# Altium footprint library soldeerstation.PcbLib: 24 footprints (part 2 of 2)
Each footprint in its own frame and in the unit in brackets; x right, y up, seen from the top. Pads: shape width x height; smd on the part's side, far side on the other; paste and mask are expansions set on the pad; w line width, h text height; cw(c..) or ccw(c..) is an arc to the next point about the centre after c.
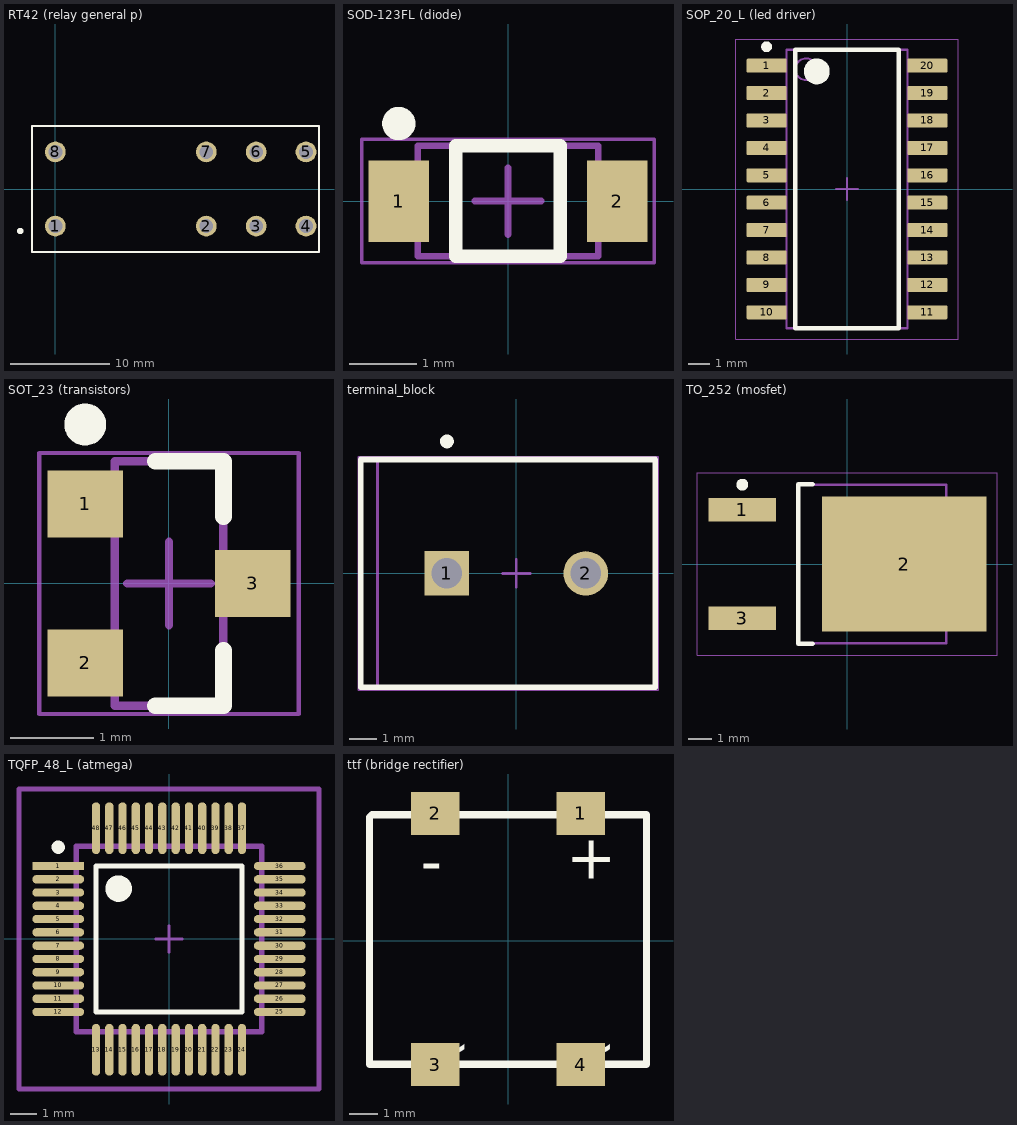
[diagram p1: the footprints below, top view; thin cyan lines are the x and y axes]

## RT42 (relay general p) [mm]
pads (8):
  round 2.1 hole 1.4: 1(0,-3.75) 2(15.26,-3.75) 3(20.3,-3.75) 4(25.34,-3.75) 5(25.34,3.75) 6(20.3,3.75) 7(15.26,3.75) 8(0,3.75)
Top Overlay:
  circle w0.4: c-3.547,-4.246 r0.126
  lines w0.2: -2.35,-6.35 -2.35,6.35 26.65,6.35 26.65,-6.35 -2.35,-6.35
Mechanical 13:
  lines w0.2: -2.35,-6.35 -2.35,6.35 26.65,6.35 26.65,-6.35 -2.35,-6.35
3D body "RT424005.stp": height 15.86, standoff -2.94, extent -2.21,-6.35 26.79,6.35

## SOD-123FL (diode) [mm] "SOD, 2-Leads, Body 2.7x1.65mm"
height 1
pads (2):
  rect 0.91x1.22 smd: 1(-1.635,0) 2(1.635,0)
Top Overlay:
  circle w0.25: c-1.635,1.16 r0.125
  lines w0.2: -0.78,-0.825 0.78,-0.825 0.78,0.825 -0.78,0.825 -0.78,-0.825
Mechanical 13:
  lines w0.1: -1.35,-0.825 1.35,-0.825 1.35,0.825 -1.35,0.825 -1.35,-0.825
Mechanical 15:
  lines w0.05: -2.19,-0.925 2.19,-0.925 2.19,0.925 -2.19,0.925 -2.19,-0.925
  lines w0.1: -0.5,0 0.5,0 ; 0,-0.5 0,0.5
3D body: height 1, standoff 0, extent -1.35,-0.825 1.35,0.825

## SOP_20_L (led driver) [mm] "SOIC,20-Leads,Body 12.9x5.6mm,Pitch 1.27mm,IPC Low Density"
height 2
pads (20):
  rrect15% 1.85x0.65 smd: 1(-3.725,5.715) 2(-3.725,4.445) 3(-3.725,3.175) 4(-3.725,1.905) 5(-3.725,0.635) 6(-3.725,-0.635) 7(-3.725,-1.905) 8(-3.725,-3.175) 9(-3.725,-4.445) 10(-3.725,-5.715) 11(3.725,-5.715) 12(3.725,-4.445) 13(3.725,-3.175) 14(3.725,-1.905) 15(3.725,-0.635) 16(3.725,0.635) 17(3.725,1.905) 18(3.725,3.175) 19(3.725,4.445) 20(3.725,5.715)
Top Overlay:
  circle w0.6: c-1.4,5.45 r0.3
  circle w0.25: c-3.725,6.59 r0.125
  lines w0.2: -2.4,-6.45 2.4,-6.45 2.4,6.45 -2.4,6.45 -2.4,-6.45
Mechanical 1:
  text ".Designator" at -1.524,-0.508 h1.02
Mechanical 13:
  circle w0.1: c-1.9,5.55 r0.5
  lines w0.1: -2.8,-6.45 2.8,-6.45 2.8,6.45 -2.8,6.45 -2.8,-6.45
Mechanical 15:
  lines w0.05: -5.15,-6.95 5.15,-6.95 5.15,6.95 -5.15,6.95 -5.15,-6.95
  lines w0.1: -0.5,0 0.5,0 ; 0,-0.5 0,0.5
3D body: height 2, standoff 0.05, extent -2.8,-6.45 2.8,6.45

## SOT_23 (transistors) [mm] "SOT23, 3-Leads, Body 2.92x1.3mm, Pitch 0.95mm"
height 1.11
pads (3):
  rect 0.9x0.8 smd: 1(-1,0.95) 2(-1,-0.95) 3(1,0)
Top Overlay:
  circle w0.25: c-1,1.9 r0.125
  lines w0.2: -0.165,-1.46 0.65,-1.46 0.65,-0.8 ; -0.165,1.46 0.65,1.46 0.65,0.8
Mechanical 13:
  lines w0.1: -0.65,-1.46 -0.65,1.46 0.65,1.46 0.65,-1.46 -0.65,-1.46
Mechanical 15:
  lines w0.05: -1.55,-1.56 -1.55,1.56 1.55,1.56 1.55,-1.56 -1.55,-1.56
  lines w0.1: -0.5,0 0.5,0 ; 0,-0.5 0,0.5
3D body: height 1.11, standoff 0.01, extent -0.65,-1.46 0.65,1.46

## terminal_block [mm] "Female Header, Pitch 5mm, 1 x 2 Position, Height 10mm"
height 10
pads (2):
  rect 1.6x1.6 hole 1.1: 1(-2.5,0)
  round 1.6 hole 1.1: 2(2.5,0)
Top Overlay:
  circle w0.25: c-2.5,4.75 r0.125
  lines w0.2: -5.6,-4.1 -5.6,4.1 5,4.1 5,-4.1 -5.6,-4.1
Mechanical 13:
  lines w0.1: -5,-4.1 5,-4.1 5,4.1 -5,4.1 -5,-4.1
Mechanical 15:
  lines w0.05: -5.7,-4.2 5.1,-4.2 5.1,4.2 -5.7,4.2 -5.7,-4.2
  lines w0.1: -0.5,0 0.5,0 ; 0,-0.5 0,0.5
3D body "c-282836-2-h-3d.stp": height 10, standoff -3.5, extent -5.6,-4.1 5,4.1

## TO_252 (mosfet) [mm] "DPAK, 3-Leads, Body 6.5x6.12mm, Pitch 2.28mm, IPC Low Density"
height 2.35
pads (3):
  rect 2.85x1 smd: 1(-4.4,2.28) 3(-4.4,-2.28)
  rect 6.9x5.65 smd: 2(2.4,0)
Top Overlay:
  circle w0.25: c-4.4,3.33 r0.125
  lines w0.2: -1.45,-3.35 -2.05,-3.35 -2.05,3.35 -1.45,3.35
Mechanical 13:
  lines w0.1: -2.05,-3.325 -2.05,3.325 4.17,3.325 4.17,-3.325 -2.05,-3.325
Mechanical 15:
  lines w0.05: -6.3,-3.825 -6.3,3.825 6.3,3.825 6.3,-3.825 -6.3,-3.825
  lines w0.1: -0.5,0 0.5,0 ; 0,-0.5 0,0.5
3D body: height 2.35, standoff 0, extent -2.05,-3.325 4.17,3.325

## TQFP_48_L (atmega) [mm]
pads (48):
  rect 1.955x0.312 smd paste+0 mask+0: 1(-4.175,2.75)
  rrect100% 1.955x0.312 smd paste+0 mask+0: 2(-4.175,2.25) 3(-4.175,1.75) 4(-4.175,1.25) 5(-4.175,0.75) 6(-4.175,0.25) 7(-4.175,-0.25) 8(-4.175,-0.75) 9(-4.175,-1.25) 10(-4.175,-1.75) 11(-4.175,-2.25) 12(-4.175,-2.75) 25(4.175,-2.75) 26(4.175,-2.25) 27(4.175,-1.75) 28(4.175,-1.25) 29(4.175,-0.75) 30(4.175,-0.25) 31(4.175,0.25) 32(4.175,0.75) 33(4.175,1.25) 34(4.175,1.75) 35(4.175,2.25) 36(4.175,2.75)
  rrect100% 0.312x1.955 smd paste+0 mask+0: 13(-2.75,-4.175) 14(-2.25,-4.175) 15(-1.75,-4.175) 16(-1.25,-4.175) 17(-0.75,-4.175) 18(-0.25,-4.175) 19(0.25,-4.175) 20(0.75,-4.175) 21(1.25,-4.175) 22(1.75,-4.175) 23(2.25,-4.175) 24(2.75,-4.175) 37(2.75,4.175) 38(2.25,4.175) 39(1.75,4.175) 40(1.25,4.175) 41(0.75,4.175) 42(0.25,4.175) 43(-0.25,4.175) 44(-0.75,4.175) 45(-1.25,4.175) 46(-1.75,4.175) 47(-2.25,4.175) 48(-2.75,4.175)
Top Overlay:
  circle w0.25: c-4.175,3.46 r0.125
  circle w0.5: c-1.9,1.9 r0.25
  lines w0.2: -2.75,-2.75 2.75,-2.75 2.75,2.75 -2.75,2.75 -2.75,-2.75
Top 3D Body:
  lines w0.2: -3.5,-3.5 3.5,-3.5 3.5,3.5 -3.5,3.5 -3.5,-3.5
Top Courtyard:
  lines w0.2: -5.653,-5.653 5.653,-5.653 5.653,5.653 -5.653,5.653 -5.653,-5.653
Top Assembly:
  lines w0.2: -5.653,-5.653 5.653,-5.653 5.653,5.653 -5.653,5.653 -5.653,-5.653
  text ".Designator" at 0,-0.001 h1
Top Component Center:
  lines w0.1: -0.5,0 0.5,0 ; 0,-0.5 0,0.5
3D body "IC_Microchip_PIC24FJ256GA705-I-PT_eec.STEP": height 0.25, standoff 0, extent -5.653,-5.653 5.653,5.653

## ttf (bridge rectifier) [mm]
pads (4):
  rect 1.7x1.5 smd: 1(2.54,4.445) 2(-2.54,4.445) 3(-2.54,-4.318) 4(2.54,-4.318)
Top Overlay:
  lines w0.254: -4.828,-4.3 -3.246,-4.3 -2.082,-4.3 0,-4.3 0.5,-4.3 4.828,-4.3 4.828,0 4.828,0.528 4.828,4.401 1.65,4.401 -1.65,4.401 -4.743,4.401 -4.828,4.316 -4.828,0.528 -4.828,-4.3
  text "~" at -3.048,-4.445 h1.52
  text "~" at 2.032,-4.445 h1.52
  text "-" at -3.048,2.032 h1.52
  text "+" at 2.032,2.159 h1.52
